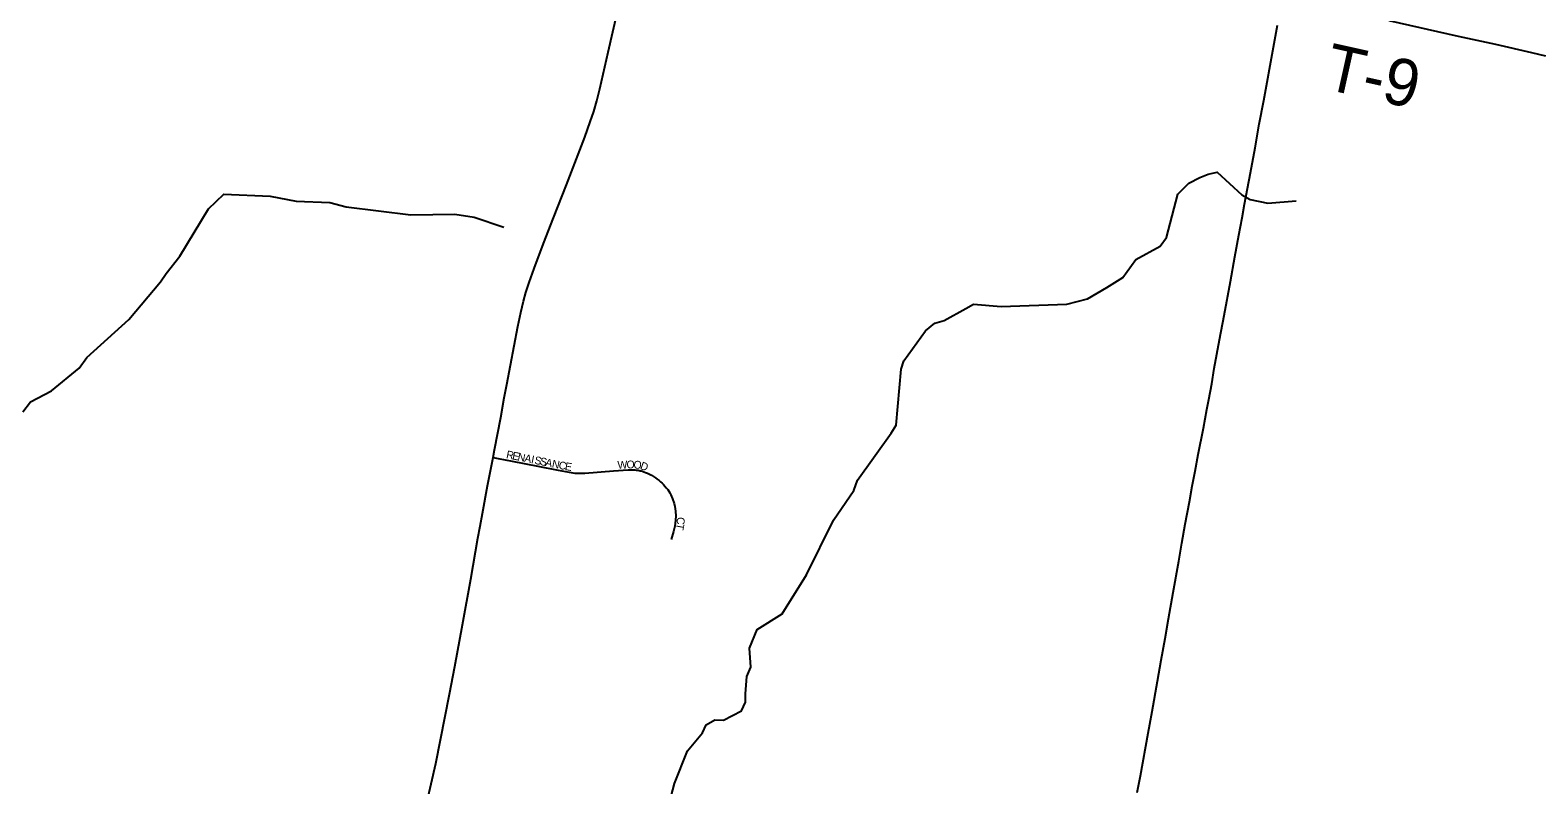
# Model space of a CAD drawing. Extents: x 1410790 to 1770854, y 448063 to 770588.
# Drawn here: x 1559967 to 1569641, y 599118 to 603957 of the extents above; entities that cross this region are included whole.
import ezdxf

# ---------------------------------------------------------------- set-up
doc = ezdxf.new("R2010")
doc.units = 0
for name, color, linetype in [('GM_X_County_Road', 7, 'Continuous'), ('GM_X_Minor_River', 7, 'Continuous'), ('GM_X_State_Route', 7, 'Continuous'), ('GM_X_Township_Road', 7, 'Continuous'), ('GM_X_Township_Road_Text', 7, 'Continuous'), ('GM_X_Township_Subdivision', 7, 'Continuous'), ('GM_X_Township_Subdivision_Text', 7, 'Continuous')]:
    doc.layers.add(name, color=color, linetype=linetype)

msp = doc.modelspace()

# ---------------------------------------------------------------- linework, layer by layer
at = {"layer": 'GM_X_County_Road'}
msp.add_lwpolyline([(1567071.1, 599069.7), (1567091.1, 599175.9), (1567141.4, 599450.2), (1567152.4, 599508.2), (1567167.3, 599588.8), (1567201.6, 599782.6), (1567224.9, 599918.5), (1567249, 600057.4), (1567271.4, 600183.3), (1567301.7, 600351.2), (1567337.6, 600551.5), (1567357.2, 600668), (1567378.9, 600790.6), (1567405.3, 600932.5), (1567424.1, 601032.4), (1567442.4, 601129.1), (1567462.6, 601235.5), (1567495.1, 601406.3), (1567517.9, 601525.4), (1567530.2, 601589.9), (1567548.6, 601690), (1567565.3, 601787), (1567599.3, 601970.7), (1567629, 602128.7), (1567668.7, 602344.9), (1567696.9, 602503.2), (1567722.3, 602642), (1567743.3, 602754.8), (1567759.8, 602841.8), (1567797, 603041.8), (1567826.5, 603203.2), (1567854.2, 603354.8), (1567882.8, 603506.3), (1567945, 603848.5), (1567971.4, 603989.6)], dxfattribs=at)
at = {"layer": 'GM_X_Minor_River'}
for points in [[(1564069.5, 599004.1), (1564101.7, 599127.8), (1564185.5, 599336.9), (1564281.6, 599451.5), (1564304.6, 599503.3), (1564361.2, 599534.4), (1564415.4, 599533.4), (1564530.7, 599593.6), (1564557.7, 599649.3), (1564556.6, 599701.4), (1564564.5, 599813.6), (1564591.6, 599873.3), (1564581.6, 599995.7), (1564631.8, 600115.2), (1564791.9, 600214.7), (1564948.5, 600464.6), (1565120.9, 600816.5), (1565252.5, 601006.7), (1565275.7, 601072.5), (1565491.3, 601373.5), (1565524.3, 601425.1), (1565556.5, 601783.5), (1565573.4, 601837.3), (1565713, 602029.4), (1565772, 602078.5), (1565832.4, 602095.5), (1565970.1, 602173.3), (1566020.7, 602200.5), (1566196.9, 602185.5), (1566618.1, 602200.2), (1566751, 602234), (1566874.6, 602308.1), (1566977.9, 602372.5), (1567062.1, 602487.3), (1567217.9, 602572.9), (1567258.9, 602628.3), (1567331.8, 602905.8), (1567401.2, 602976.8), (1567472, 603011.6), (1567526.5, 603034.8), (1567582.8, 603045.8), (1567742.7, 602900.7), (1567794.4, 602871.7), (1567908.2, 602847.7), (1568090.9, 602862.6)], [(1559920.2, 601509.7), (1559969.5, 601575), (1560103, 601644.9), (1560281.9, 601790.2), (1560331.2, 601857.5), (1560600, 602101.5), (1560802.6, 602344.6), (1560839.6, 602396.1), (1560927.7, 602508.9), (1561111.3, 602812.5), (1561209.1, 602905.1), (1561505.7, 602893.9), (1561673.5, 602861), (1561889.9, 602853.3), (1561993.7, 602825.4), (1562409.8, 602774.1), (1562692.5, 602777.3), (1562816.5, 602759.1), (1563005.9, 602693.7)]]:
    msp.add_lwpolyline(points, dxfattribs=at)
at = {"layer": 'GM_X_State_Route'}
msp.add_lwpolyline([(1562520.4, 599041), (1562540.4, 599123.8), (1562569.2, 599255.1), (1562599.8, 599406.2), (1562656.7, 599699.3), (1562691.6, 599876.3), (1562740.9, 600144), (1562795, 600437.5), (1562839.3, 600699.7), (1562854.3, 600777), (1562869.6, 600857.5), (1562901.7, 601035.1), (1562936.7, 601217.8), (1562946.2, 601267.1), (1562986.2, 601473.2), (1563009, 601599), (1563024.7, 601686.3), (1563095, 602057), (1563114.2, 602147), (1563132.1, 602220.5), (1563147.4, 602274.3), (1563168.8, 602339.9), (1563200.6, 602429.8), (1563260.8, 602589.4), (1563324.6, 602754.8), (1563408.2, 602965.1), (1563525.7, 603271.4), (1563561.2, 603370.1), (1563582.7, 603435.4), (1563602.9, 603504.4), (1563622.2, 603580.6), (1563676.3, 603817.2), (1563742.4, 604105)], dxfattribs=at)
at = {"layer": 'GM_X_Township_Road'}
msp.add_lwpolyline([(1568685.9, 604019.1), (1569129.9, 603919.2), (1569369.2, 603867.8), (1569601.7, 603813.4), (1569690.6, 603793.5)], dxfattribs=at)
at = {"layer": 'GM_X_Township_Subdivision'}
msp.add_lwpolyline([(1562936.7, 601217.8), (1562969.3, 601211.2), (1563059.3, 601193.2), (1563223.4, 601160.9), (1563355.3, 601135.1), (1563426, 601122.2), (1563461.5, 601117.6), (1563493.8, 601115.8), (1563526.2, 601116.5), (1563709.1, 601131.4), (1563804.3, 601137.3), (1563822.6, 601138.1), (1563836.5, 601138.1), (1563846.2, 601137.6), (1563855.2, 601137), (1563862.2, 601136.2), (1563868.3, 601135.3), (1563875.3, 601134), (1563881.7, 601132.6), (1563888.3, 601130.9), (1563895, 601128.9), (1563904.5, 601125.9), (1563916.2, 601121.4), (1563927.1, 601116.9), (1563940.1, 601110.5), (1563953.6, 601103.6), (1563966.3, 601095.9), (1563979.3, 601087.4), (1563991.1, 601079.1), (1564002.1, 601070.7), (1564011.8, 601062.3), (1564021.7, 601053.6), (1564031.1, 601043.9), (1564040, 601034.4), (1564048.6, 601023.8), (1564057.6, 601012.4), (1564064.9, 601001.8), (1564071, 600990.9), (1564077.3, 600978.7), (1564089.5, 600951.4), (1564099.5, 600923), (1564104, 600903.4), (1564107.8, 600873.7), (1564109.3, 600840.5), (1564108.2, 600817.1), (1564106.1, 600797.1), (1564102.6, 600777.8), (1564099, 600759.5), (1564095, 600742.2), (1564080.5, 600691.4)], dxfattribs=at)

# ---------------------------------------------------------------- texts
at = {"layer": 'GM_X_Township_Road_Text'}
msp.add_text('T-9', height=300, rotation=347.47258, dxfattribs=at).set_placement((1568258.4, 603582.9))
at = {"layer": 'GM_X_Township_Subdivision_Text'}
for s, rotation, p in [('R', 348.55669, (1563018.5, 601214)), ('E', 348.56698, (1563057.3, 601206.2)), ('N', 348.57614, (1563091.8, 601199.2)), ('A', 348.55717, (1563135, 601190.5)), ('I', 348.54672, (1563178.1, 601181.8)), ('S', 348.55149, (1563199.7, 601177.4)), ('S', 348.56698, (1563234.1, 601170.4)), ('A', 348.57614, (1563268.7, 601163.4)), ('N', 348.55717, (1563311.8, 601154.7)), ('O', 0.69949, (1563793.9, 601147.3)), ('C', 348.5528, (1563354.9, 601146)), ('E', 350.30346, (1563395.4, 601137.8)), ('W', 3.53333, (1563737.5, 601143.8)), ('O', 354.96587, (1563836.6, 601147.9)), ('D', 340.38294, (1563877.2, 601144.7)), ('C', 268.39671, (1564117.2, 600835.6)), ('T', 259.19908, (1564116.3, 600798.1))]:
    msp.add_text(s, height=50, rotation=rotation, dxfattribs=at).set_placement(p)

doc.saveas('drawing.dxf')
